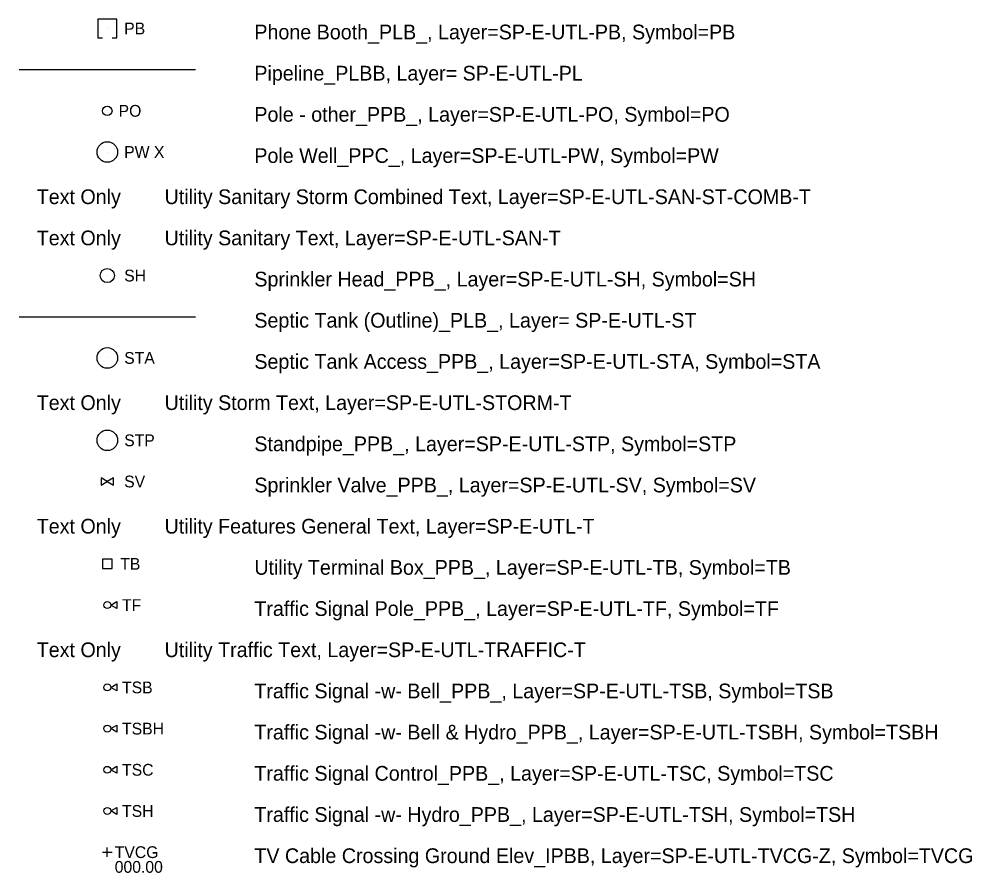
# Model space of a CAD drawing. Extents: x 500528 to 502626, y 4210261 to 4212624.
# Drawn here: x 500886.5 to 501048.5, y 4210705.1 to 4210850.2 of the extents above; entities that cross this region are included whole.
import ezdxf

# ---------------------------------------------------------------- set-up
doc = ezdxf.new("R2010")
doc.units = 0
for name, color, linetype in [('SP-E-UTL-COMB-T', 7, 'Continuous'), ('SP-E-UTL-PB', 7, 'Continuous'), ('SP-E-UTL-PL', 7, 'Continuous'), ('SP-E-UTL-PO', 7, 'Continuous'), ('SP-E-UTL-PW', 7, 'Continuous'), ('SP-E-UTL-SAN-ST-COMB-T', 7, 'Continuous'), ('SP-E-UTL-SAN-T', 7, 'Continuous'), ('SP-E-UTL-SH', 7, 'Continuous'), ('SP-E-UTL-ST', 7, 'Continuous'), ('SP-E-UTL-STA', 7, 'Continuous'), ('SP-E-UTL-STORM-T', 7, 'Continuous'), ('SP-E-UTL-STP', 7, 'Continuous'), ('SP-E-UTL-SV', 7, 'Continuous'), ('SP-E-UTL-T', 7, 'Continuous'), ('SP-E-UTL-TB', 7, 'Continuous'), ('SP-E-UTL-TF', 7, 'Continuous'), ('SP-E-UTL-TRAFFIC-T', 7, 'Continuous'), ('SP-E-UTL-TSB', 7, 'Continuous'), ('SP-E-UTL-TSBH', 7, 'Continuous'), ('SP-E-UTL-TSC', 7, 'Continuous'), ('SP-E-UTL-TSH', 7, 'Continuous'), ('SP-E-UTL-TV-T', 7, 'Continuous'), ('SP-E-UTL-TVCG-Z', 7, 'Continuous')]:
    doc.layers.add(name, color=color, linetype=linetype)

# ---------------------------------------------------------------- blocks, each defined once
blk = doc.blocks.new('PB')
at = {"layer": 'SP-E-UTL-PB'}
for points in [[(0.08, -0.16), (0.16, -0.16), (0.16, 0.16), (-0.16, 0.16), (-0.16, -0.16), (-0.08, -0.16)], [(0, 0), (0, 0)]]:
    blk.add_lwpolyline(points, dxfattribs=at)
at = {"layer": 'SP-E-UTL-T'}
blk.add_text('PB', height=0.2, dxfattribs=at).set_placement((0.287, -0.1))
blk = doc.blocks.new('PO')
at = {"layer": 'SP-E-UTL-PO'}
blk.add_lwpolyline([(0, 0), (0, 0)], dxfattribs=at)
blk.add_circle((0, 0), 0.08, dxfattribs=at)
at = {"layer": 'SP-E-UTL-T'}
blk.add_text('PO', height=0.2, dxfattribs=at).set_placement((0.192, -0.1))
blk = doc.blocks.new('PW')
at = {"layer": 'SP-E-UTL-PW'}
blk.add_lwpolyline([(0, 0), (0, 0)], dxfattribs=at)
blk.add_circle((0, 0), 0.175, dxfattribs=at)
at = {"layer": 'SP-E-UTL-T'}
blk.add_text('PW X', height=0.2, dxfattribs=at).set_placement((0.287, -0.1))
blk = doc.blocks.new('SH')
at = {"layer": 'SP-E-UTL-SH'}
blk.add_lwpolyline([(0, 0), (0, 0)], dxfattribs=at)
blk.add_circle((0, 0), 0.12, dxfattribs=at)
at = {"layer": 'SP-E-UTL-T'}
blk.add_text('SH', height=0.2, dxfattribs=at).set_placement((0.287, -0.1))
blk = doc.blocks.new('STA')
at = {"layer": 'SP-E-UTL-STA'}
blk.add_lwpolyline([(0, 0), (0, 0)], dxfattribs=at)
blk.add_circle((0, 0), 0.175, dxfattribs=at)
at = {"layer": 'SP-E-UTL-T'}
blk.add_text('STA', height=0.2, dxfattribs=at).set_placement((0.287, -0.1))
blk = doc.blocks.new('STP')
at = {"layer": 'SP-E-UTL-STP'}
blk.add_lwpolyline([(0, 0), (0, 0)], dxfattribs=at)
blk.add_circle((0, 0), 0.175, dxfattribs=at)
at = {"layer": 'SP-E-UTL-T'}
blk.add_text('STP', height=0.2, dxfattribs=at).set_placement((0.287, -0.1))
blk = doc.blocks.new('SV')
at = {"layer": 'SP-E-UTL-SV'}
for points in [[(-0.104, -0.06), (0, 0), (-0.104, 0.06), (-0.104, -0.06)], [(0.104, -0.06), (0.104, 0.06), (0, 0), (0.104, -0.06)]]:
    blk.add_lwpolyline(points, dxfattribs=at)
at = {"layer": 'SP-E-UTL-T'}
blk.add_text('SV', height=0.2, dxfattribs=at).set_placement((0.287, -0.1))
blk = doc.blocks.new('TB')
at = {"layer": 'SP-E-UTL-TB'}
for points in [[(-0.08, 0.08), (-0.08, -0.08), (0.08, -0.08), (0.08, 0.08), (-0.08, 0.08)], [(0, 0), (0, 0)]]:
    blk.add_lwpolyline(points, dxfattribs=at)
at = {"layer": 'SP-E-UTL-T'}
blk.add_text('TB', height=0.2, dxfattribs=at).set_placement((0.22, -0.1))
blk = doc.blocks.new('TF')
at = {"layer": 'SP-E-UTL-TF'}
for points in [[(0, 0), (0, 0)], [(0.058, 0), (0.162, 0.06), (0.162, -0.06), (0.058, 0)]]:
    blk.add_lwpolyline(points, dxfattribs=at)
blk.add_circle((0, 0), 0.0585, dxfattribs=at)
at = {"layer": 'SP-E-UTL-TRAFFIC-T'}
blk.add_text('TF', height=0.2, dxfattribs=at).set_placement((0.251, -0.1))
blk = doc.blocks.new('TSB')
at = {"layer": 'SP-E-UTL-TSB'}
for points in [[(0, 0), (0, 0)], [(0.058, 0), (0.162, 0.06), (0.162, -0.06), (0.058, 0)]]:
    blk.add_lwpolyline(points, dxfattribs=at)
blk.add_circle((0, 0), 0.0585, dxfattribs=at)
at = {"layer": 'SP-E-UTL-COMB-T'}
blk.add_text('TSB', height=0.2, dxfattribs=at).set_placement((0.251, -0.1))
blk = doc.blocks.new('TSBH')
at = {"layer": 'SP-E-UTL-TSBH'}
for points in [[(0, 0), (0, 0)], [(0.058, 0), (0.162, 0.06), (0.162, -0.06), (0.058, 0)]]:
    blk.add_lwpolyline(points, dxfattribs=at)
blk.add_circle((0, 0), 0.0585, dxfattribs=at)
at = {"layer": 'SP-E-UTL-COMB-T'}
blk.add_text('TSBH', height=0.2, dxfattribs=at).set_placement((0.251, -0.1))
blk = doc.blocks.new('TSC')
at = {"layer": 'SP-E-UTL-TSC'}
for points in [[(0, 0), (0, 0)], [(0.058, 0), (0.162, 0.06), (0.162, -0.06), (0.058, 0)]]:
    blk.add_lwpolyline(points, dxfattribs=at)
blk.add_circle((0, 0), 0.0585, dxfattribs=at)
at = {"layer": 'SP-E-UTL-TRAFFIC-T'}
blk.add_text('TSC', height=0.2, dxfattribs=at).set_placement((0.251, -0.1))
blk = doc.blocks.new('TSH')
at = {"layer": 'SP-E-UTL-TSH'}
for points in [[(0, 0), (0, 0)], [(0.058, 0), (0.162, 0.06), (0.162, -0.06), (0.058, 0)]]:
    blk.add_lwpolyline(points, dxfattribs=at)
blk.add_circle((0, 0), 0.0585, dxfattribs=at)
at = {"layer": 'SP-E-UTL-COMB-T'}
blk.add_text('TSH', height=0.2, dxfattribs=at).set_placement((0.251, -0.1))
blk = doc.blocks.new('TVCG')
at = {"layer": 'SP-E-UTL-TVCG-Z'}
for points in [[(-0.08, 0), (0.08, 0)], [(0, -0.08), (0, 0.08)]]:
    blk.add_lwpolyline(points, dxfattribs=at)
at = {"layer": 'SP-E-UTL-TV-T'}
for s, p in [('TVCG', (0.126, -0.1)), ('000.00', (0.126, -0.35))]:
    blk.add_text(s, height=0.2, dxfattribs=at).set_placement(p)

msp = doc.modelspace()

# ---------------------------------------------------------------- linework, layer by layer
at = {"layer": 'SP-E-UTL-PL'}
msp.add_line((500886.55, 4210841.59), (500916.55, 4210841.59), dxfattribs=at)
at = {"layer": 'SP-E-UTL-ST'}
msp.add_line((500886.55, 4210799.59), (500916.55, 4210799.59), dxfattribs=at)

# ---------------------------------------------------------------- block references
at = {"layer": 'SP-E-UTL-PB', "xscale": 10, "yscale": 10}
msp.add_blockref('PB', (500901.55, 4210848.59), dxfattribs=at)
at = {"layer": 'SP-E-UTL-PO', "xscale": 10, "yscale": 10}
msp.add_blockref('PO', (500901.55, 4210834.59), dxfattribs=at)
at = {"layer": 'SP-E-UTL-PW', "xscale": 10, "yscale": 10}
msp.add_blockref('PW', (500901.55, 4210827.59), dxfattribs=at)
at = {"layer": 'SP-E-UTL-SH', "xscale": 10, "yscale": 10}
msp.add_blockref('SH', (500901.55, 4210806.59), dxfattribs=at)
at = {"layer": 'SP-E-UTL-STA', "xscale": 10, "yscale": 10}
msp.add_blockref('STA', (500901.55, 4210792.59), dxfattribs=at)
at = {"layer": 'SP-E-UTL-STP', "xscale": 10, "yscale": 10}
msp.add_blockref('STP', (500901.55, 4210778.59), dxfattribs=at)
at = {"layer": 'SP-E-UTL-SV', "xscale": 10, "yscale": 10}
msp.add_blockref('SV', (500901.55, 4210771.59), dxfattribs=at)
at = {"layer": 'SP-E-UTL-TB', "xscale": 10, "yscale": 10}
msp.add_blockref('TB', (500901.55, 4210757.59), dxfattribs=at)
at = {"layer": 'SP-E-UTL-TF', "xscale": 10, "yscale": 10}
msp.add_blockref('TF', (500901.55, 4210750.59), dxfattribs=at)
at = {"layer": 'SP-E-UTL-TSB', "xscale": 10, "yscale": 10}
msp.add_blockref('TSB', (500901.55, 4210736.59), dxfattribs=at)
at = {"layer": 'SP-E-UTL-TSBH', "xscale": 10, "yscale": 10}
msp.add_blockref('TSBH', (500901.55, 4210729.59), dxfattribs=at)
at = {"layer": 'SP-E-UTL-TSC', "xscale": 10, "yscale": 10}
msp.add_blockref('TSC', (500901.55, 4210722.59), dxfattribs=at)
at = {"layer": 'SP-E-UTL-TSH', "xscale": 10, "yscale": 10}
msp.add_blockref('TSH', (500901.55, 4210715.59), dxfattribs=at)
at = {"layer": 'SP-E-UTL-TVCG-Z', "xscale": 10, "yscale": 10}
msp.add_blockref('TVCG', (500901.55, 4210708.59), dxfattribs=at)

# ---------------------------------------------------------------- texts
at = {"layer": 'SP-E-UTL-PB'}
msp.add_text('Phone Booth_PLB_, Layer=SP-E-UTL-PB, Symbol=PB ', height=2.5, dxfattribs=at).set_placement((500926.55, 4210846.74))
at = {"layer": 'SP-E-UTL-PL'}
msp.add_text('Pipeline_PLBB, Layer= SP-E-UTL-PL ', height=2.5, dxfattribs=at).set_placement((500926.55, 4210839.74))
at = {"layer": 'SP-E-UTL-PO'}
msp.add_text('Pole - other_PPB_, Layer=SP-E-UTL-PO, Symbol=PO ', height=2.5, dxfattribs=at).set_placement((500926.55, 4210832.74))
at = {"layer": 'SP-E-UTL-PW'}
msp.add_text('Pole Well_PPC_, Layer=SP-E-UTL-PW, Symbol=PW ', height=2.5, dxfattribs=at).set_placement((500926.55, 4210825.74))
at = {"layer": 'SP-E-UTL-SAN-ST-COMB-T'}
msp.add_text('Text Only        Utility Sanitary Storm Combined Text, Layer=SP-E-UTL-SAN-ST-COMB-T', height=2.5, dxfattribs=at).set_placement((500889.55, 4210818.74))
at = {"layer": 'SP-E-UTL-SAN-T'}
msp.add_text('Text Only        Utility Sanitary Text, Layer=SP-E-UTL-SAN-T', height=2.5, dxfattribs=at).set_placement((500889.55, 4210811.74))
at = {"layer": 'SP-E-UTL-SH'}
msp.add_text('Sprinkler Head_PPB_, Layer=SP-E-UTL-SH, Symbol=SH ', height=2.5, dxfattribs=at).set_placement((500926.55, 4210804.74))
at = {"layer": 'SP-E-UTL-ST'}
msp.add_text('Septic Tank (Outline)_PLB_, Layer= SP-E-UTL-ST ', height=2.5, dxfattribs=at).set_placement((500926.55, 4210797.74))
at = {"layer": 'SP-E-UTL-STA'}
msp.add_text('Septic Tank Access_PPB_, Layer=SP-E-UTL-STA, Symbol=STA ', height=2.5, dxfattribs=at).set_placement((500926.55, 4210790.74))
at = {"layer": 'SP-E-UTL-STORM-T'}
msp.add_text('Text Only        Utility Storm Text, Layer=SP-E-UTL-STORM-T', height=2.5, dxfattribs=at).set_placement((500889.55, 4210783.74))
at = {"layer": 'SP-E-UTL-STP'}
msp.add_text('Standpipe_PPB_, Layer=SP-E-UTL-STP, Symbol=STP ', height=2.5, dxfattribs=at).set_placement((500926.55, 4210776.74))
at = {"layer": 'SP-E-UTL-SV'}
msp.add_text('Sprinkler Valve_PPB_, Layer=SP-E-UTL-SV, Symbol=SV ', height=2.5, dxfattribs=at).set_placement((500926.55, 4210769.74))
at = {"layer": 'SP-E-UTL-T'}
msp.add_text('Text Only        Utility Features General Text, Layer=SP-E-UTL-T', height=2.5, dxfattribs=at).set_placement((500889.55, 4210762.74))
at = {"layer": 'SP-E-UTL-TB'}
msp.add_text('Utility Terminal Box_PPB_, Layer=SP-E-UTL-TB, Symbol=TB ', height=2.5, dxfattribs=at).set_placement((500926.55, 4210755.74))
at = {"layer": 'SP-E-UTL-TF'}
msp.add_text('Traffic Signal Pole_PPB_, Layer=SP-E-UTL-TF, Symbol=TF ', height=2.5, dxfattribs=at).set_placement((500926.55, 4210748.74))
at = {"layer": 'SP-E-UTL-TRAFFIC-T'}
msp.add_text('Text Only        Utility Traffic Text, Layer=SP-E-UTL-TRAFFIC-T', height=2.5, dxfattribs=at).set_placement((500889.55, 4210741.74))
at = {"layer": 'SP-E-UTL-TSB'}
msp.add_text('Traffic Signal -w- Bell_PPB_, Layer=SP-E-UTL-TSB, Symbol=TSB ', height=2.5, dxfattribs=at).set_placement((500926.55, 4210734.74))
at = {"layer": 'SP-E-UTL-TSBH'}
msp.add_text('Traffic Signal -w- Bell & Hydro_PPB_, Layer=SP-E-UTL-TSBH, Symbol=TSBH ', height=2.5, dxfattribs=at).set_placement((500926.55, 4210727.74))
at = {"layer": 'SP-E-UTL-TSC'}
msp.add_text('Traffic Signal Control_PPB_, Layer=SP-E-UTL-TSC, Symbol=TSC ', height=2.5, dxfattribs=at).set_placement((500926.55, 4210720.74))
at = {"layer": 'SP-E-UTL-TSH'}
msp.add_text('Traffic Signal -w- Hydro_PPB_, Layer=SP-E-UTL-TSH, Symbol=TSH ', height=2.5, dxfattribs=at).set_placement((500926.55, 4210713.74))
at = {"layer": 'SP-E-UTL-TVCG-Z'}
msp.add_text('TV Cable Crossing Ground Elev_IPBB, Layer=SP-E-UTL-TVCG-Z, Symbol=TVCG ', height=2.5, dxfattribs=at).set_placement((500926.55, 4210706.74))

doc.saveas('drawing.dxf')
